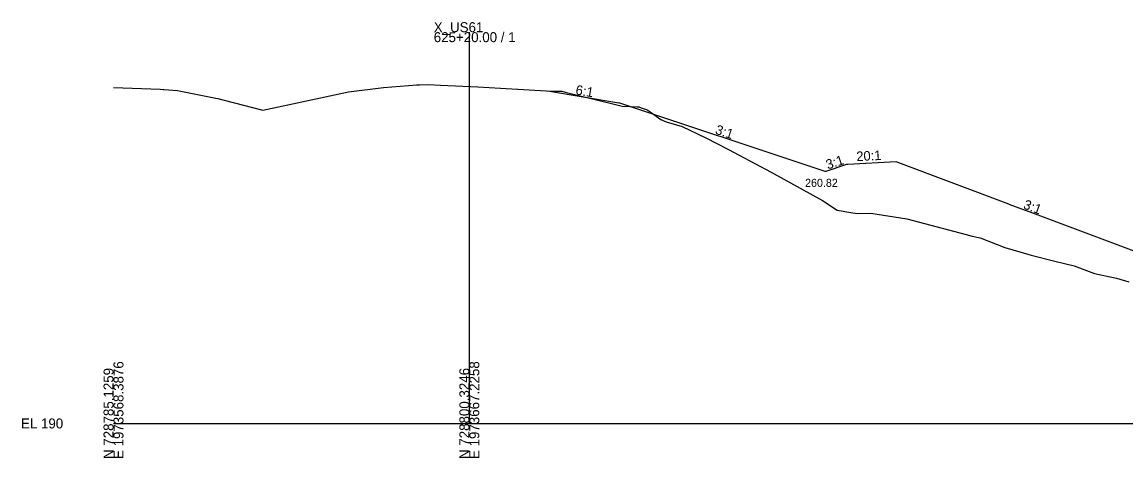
# Model space of a CAD drawing. Extents: x -26 to 630, y -39 to 9098.
# Drawn here: x -25.7 to 284.5, y 2990.3 to 3112.8 of the extents above; entities that cross this region are included whole.
import ezdxf

# ---------------------------------------------------------------- set-up
doc = ezdxf.new("R2010")
doc.units = 0
for name, color, linetype in [('Default', 7, 'Continuous'), ('Draft_XS_Grid', 7, 'Continuous'), ('DTM CONTOURS_MAJOR', 7, 'Continuous'), ('DTM_X_GROUND', 7, 'Continuous'), ('X_DTM_CONTOURS_MAJOR', 7, 'Continuous'), ('XS_CELL', 7, 'Continuous'), ('XS_P_GROUND', 7, 'Continuous'), ('XS_P_TX_DCH', 7, 'Continuous'), ('XS_P_TX_FS_BS', 7, 'Continuous')]:
    doc.layers.add(name, color=color, linetype=linetype)

msp = doc.modelspace()

# ---------------------------------------------------------------- linework, layer by layer
at = {"layer": 'DTM_X_GROUND'}
msp.add_lwpolyline([(0, 3094.43), (13.14, 3093.95), (13.96, 3093.92), (14.18, 3093.9), (18, 3093.6), (28.77, 3091.46), (29.3, 3091.35), (31.06, 3090.93), (41.93, 3088.09), (47.64, 3089.31), (66.05, 3093.2), (75.86, 3094.42), (85.24, 3095.2), (85.95, 3095.22), (88.47, 3095.29), (91.87, 3095.13), (102.42, 3094.61), (121.63, 3093.51), (123.43, 3093.41), (123.66, 3093.41), (125.95, 3093.38), (126.96, 3093.17), (141.11, 3089.67), (142.93, 3089.22), (147.18, 3088.98), (147.61, 3088.99), (148.32, 3088.74), (148.82, 3088.56), (149.76, 3088.22), (150.16, 3088.08), (153.8, 3085.48), (155.36, 3084.81), (158.26, 3083.96), (159.81, 3083.51), (166.46, 3080.26), (172.81, 3077.01), (180.28, 3073.1), (184.87, 3070.64), (199.27, 3062.71), (203.39, 3059.99), (207.26, 3059.31), (208.96, 3059.04), (212.81, 3059.09), (222.99, 3057.52), (239.62, 3053.1), (241.3, 3052.68), (243.59, 3052.18), (250.45, 3049.45), (257.91, 3047.3), (264.52, 3045.63), (269.93, 3044.35), (275.69, 3042.11), (281.91, 3040.81), (285.31, 3039.78)], dxfattribs=at)
at = {"layer": 'XS_CELL'}
for p, q in [((100, 3000), (100, 3110)), ((0, 3000), (100, 3000)), ((100, 3000), (450, 3000))]:
    msp.add_line(p, q, dxfattribs=at)
at = {"layer": 'XS_P_GROUND'}
for points in [[(122, 3093.49), (142, 3090.15)], [(313.59, 3047.92), (312.72, 3047.88), (312.65, 3047.88), (311.48, 3047.82), (311.44, 3047.82), (310.29, 3047.76), (310.23, 3047.76), (308.01, 3047.64), (307.69, 3047.63), (301.07, 3047.3), (295.22, 3045.35), (295.07, 3045.3), (258.32, 3059.11), (257.29, 3059.5), (251.73, 3061.59), (251.58, 3061.65), (220.72, 3073.25), (220, 3073.52), (206.35, 3072.84), (206, 3072.82), (200.15, 3070.87), (200, 3070.82), (198.57, 3071.3), (142, 3090.15)]]:
    msp.add_lwpolyline(points, dxfattribs=at)

# ---------------------------------------------------------------- texts
at = {"layer": 'Default'}
msp.add_text('X', height=0.12, dxfattribs=at).set_placement((199.96, 3070.76))
msp.add_text('X', height=0.12, dxfattribs=at).set_placement((199.96, 3070.76))
at = {"layer": 'Draft_XS_Grid'}
msp.add_text('-', height=0.0001, dxfattribs=at).set_placement((0, 3000))
at = {"layer": 'DTM CONTOURS_MAJOR'}
msp.add_text('X', height=0.001, dxfattribs=at).set_placement((200, 3070.82))
at = {"layer": 'X_DTM_CONTOURS_MAJOR'}
for height, p in [(0.12, (121.96, 3093.43)), (0.12, (141.96, 3090.09)), (0.12, (205.96, 3072.76)), (0.12, (205.96, 3072.76)), (0.001, (206, 3072.82)), (0.12, (219.96, 3073.46)), (0.12, (219.96, 3073.46)), (0.001, (220, 3073.52))]:
    msp.add_text('X', height=height, dxfattribs=at).set_placement(p)
at = {"layer": 'XS_CELL'}
for s, p in [('X_US61', (90, 3110)), ('625+20.00 / 1', (90, 3107.2)), ('EL 190', (-26, 2998.6))]:
    msp.add_text(s, height=2.8, dxfattribs=at).set_placement(p)
for s, p in [('N 728785.1259', (0, 2990)), ('E 1973568.3876', (2.8, 2990)), ('N 728800.3246', (100, 2990)), ('E 1973667.2258', (102.8, 2990))]:
    msp.add_text(s, height=2.8, rotation=90, dxfattribs=at).set_placement(p)
at = {"layer": 'XS_P_TX_DCH'}
msp.add_text('260.82', height=2.25, dxfattribs=at).set_placement((194.35, 3066.52))
at = {"layer": 'XS_P_TX_FS_BS'}
for s, rotation, p in [('6:1', 350.5377, (129.72, 3092.51)), ('3:1', 341.5651, (168.92, 3081.5)), ('3:1', 18.4349, (200.73, 3071.38)), ('20:1', 2.8625, (208.83, 3073.73)), ('3:1', 339.396, (255.49, 3060.5))]:
    msp.add_text(s, height=2.7, rotation=rotation, dxfattribs=at).set_placement(p)

doc.saveas('drawing.dxf')
